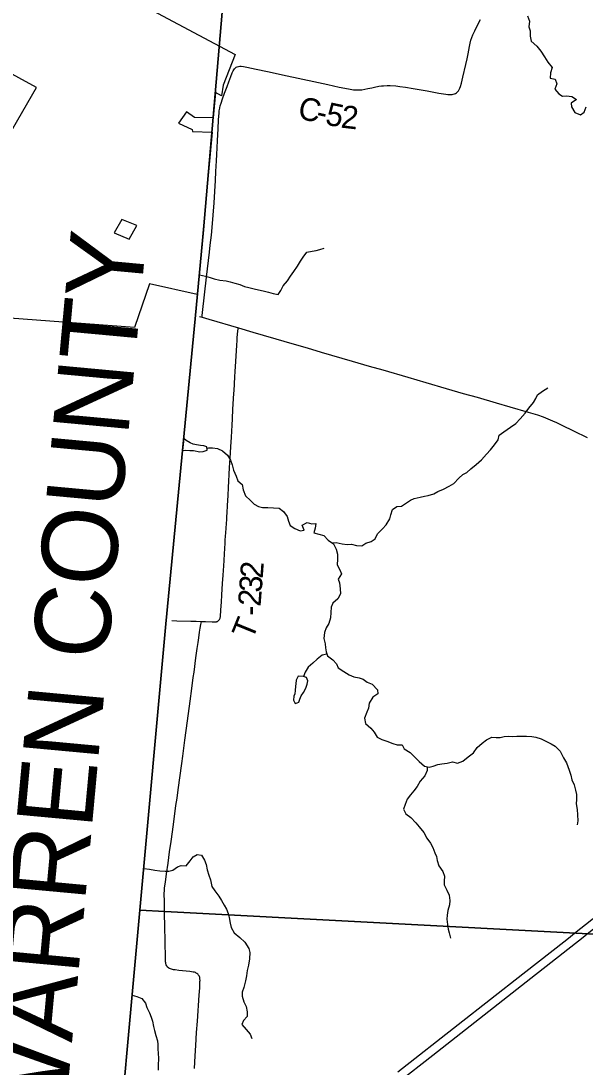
# Model space of a CAD drawing. Extents: x 1442749 to 1756758, y 235267 to 677782.
# Drawn here: x 1547500 to 1554943, y 538726 to 552520 of the extents above; entities that cross this region are included whole.
import ezdxf

# ---------------------------------------------------------------- set-up
doc = ezdxf.new("R2010")
doc.units = 0
for name, color, linetype in [('GM_X_Adjacent_County', 7, 'Continuous'), ('GM_X_Adjacent_County_Text', 7, 'Continuous'), ('GM_X_Corporation', 7, 'Continuous'), ('GM_X_County', 7, 'Continuous'), ('GM_X_County_Road', 7, 'Continuous'), ('GM_X_County_Road_Text', 7, 'Continuous'), ('GM_X_Interstate_Route', 7, 'Continuous'), ('GM_X_Minor_Lake', 7, 'Continuous'), ('GM_X_Minor_River', 7, 'Continuous'), ('GM_X_State_Route', 7, 'Continuous'), ('GM_X_Township', 7, 'Continuous'), ('GM_X_Township_Road', 7, 'Continuous'), ('GM_X_Township_Road_Text', 7, 'Continuous')]:
    doc.layers.add(name, color=color, linetype=linetype)

msp = doc.modelspace()

# ---------------------------------------------------------------- linework, layer by layer
at = {"layer": 'GM_X_Adjacent_County'}
msp.add_lwpolyline([(1551044, 562988), (1549909, 549765), (1549797, 548590), (1549411, 544570), (1549068, 540794), (1548703, 536779), (1548609, 535719), (1548059, 529500), (1548052, 529426), (1547777, 526306), (1547463, 522758), (1547324, 521188), (1546926, 516687), (1546686, 513989), (1546298, 509606), (1545822, 504298), (1545798, 504044), (1545353, 499331)], dxfattribs=at)
at = {"layer": 'GM_X_Corporation'}
for points in [[(1548824, 552881), (1550326, 552078), (1550169, 551671), (1550148, 551531), (1550065, 551575), (1550037, 551241), (1549790, 551245), (1549683, 551323), (1549577, 551172), (1549761, 551087), (1549763, 551063), (1550021, 551055), (1549823, 548911), (1549194, 549054), (1548997, 548479), (1546410, 548672)], [(1547391, 551101), (1547704, 551643), (1546537, 552279)]]:
    msp.add_lwpolyline(points, dxfattribs=at)
msp.add_lwpolyline([(1548732, 549726), (1548928, 549643), (1549031, 549821), (1548833, 549901)], close=True, dxfattribs=at)
at = {"layer": 'GM_X_County'}
msp.add_lwpolyline([(1545353, 499331), (1545798, 504044), (1545822, 504298), (1546298, 509606), (1546686, 513989), (1546926, 516687), (1547324, 521188), (1547463, 522758), (1547777, 526306), (1548052, 529426), (1548059, 529500), (1548609, 535719), (1548703, 536779), (1549068, 540794), (1549411, 544570), (1549797, 548590), (1549909, 549765), (1551044, 562988)], dxfattribs=at)
at = {"layer": 'GM_X_County_Road'}
msp.add_lwpolyline([(1549889, 548612), (1549891, 548636), (1549896, 548677), (1549950, 549139), (1549988, 549471), (1549998, 549562), (1550014, 549696), (1550023, 549794), (1550037, 549957), (1550048, 550120), (1550059, 550271), (1550067, 550415), (1550073, 550536), (1550078, 550677), (1550083, 550759), (1550089, 550847), (1550095, 550945), (1550102, 551096), (1550107, 551217), (1550114, 551306), (1550117, 551335), (1550123, 551368), (1550124, 551374), (1550129, 551399), (1550141, 551436), (1550159, 551491), (1550187, 551568), (1550221, 551657), (1550242, 551716), (1550270, 551789), (1550288, 551835), (1550299, 551860), (1550307, 551874), (1550317, 551888), (1550329, 551900), (1550341, 551908), (1550353, 551915), (1550369, 551920), (1550386, 551922), (1550407, 551922), (1550436, 551919), (1550482, 551911), (1550604, 551885), (1550755, 551853), (1551011, 551797), (1551364, 551722), (1551547, 551680), (1551700, 551647), (1551774, 551632), (1551842, 551619), (1551887, 551612), (1551926, 551610), (1551961, 551610), (1551997, 551613), (1552036, 551618), (1552077, 551627), (1552128, 551639), (1552166, 551648), (1552221, 551658), (1552257, 551663), (1552283, 551665), (1552333, 551667), (1552372, 551666), (1552445, 551662), (1552500, 551655), (1552575, 551645), (1552675, 551628), (1552859, 551596), (1553014, 551569), (1553075, 551558), (1553104, 551554), (1553130, 551551), (1553140, 551550), (1553162, 551549), (1553188, 551550), (1553204, 551552), (1553218, 551557), (1553232, 551564), (1553245, 551573), (1553260, 551586), (1553272, 551600), (1553283, 551616), (1553291, 551633), (1553299, 551654), (1553312, 551701), (1553330, 551778), (1553370, 551943), (1553388, 552020), (1553400, 552084), (1553416, 552181), (1553425, 552226), (1553435, 552264), (1553448, 552302), (1553463, 552338), (1553487, 552389), (1553516, 552447), (1553562, 552540)], dxfattribs=at)
at = {"layer": 'GM_X_Interstate_Route'}
for points in [[(1552472, 538521), (1552934, 538884), (1553241, 539126), (1554227, 539899), (1554916, 540439), (1554992, 540498), (1555622, 540996), (1556053, 541330), (1556350, 541552), (1556686, 541792), (1557003, 542010), (1557397, 542269), (1557719, 542473), (1558089, 542698), (1558328, 542835), (1558833, 543115), (1559231, 543325), (1559521, 543470), (1560001, 543699), (1560259, 543815), (1560468, 543909), (1560773, 544039), (1561542, 544359)], [(1552473, 538663), (1553270, 539288), (1554122, 539957), (1554700, 540410), (1554825, 540509), (1555156, 540770)]]:
    msp.add_lwpolyline(points, dxfattribs=at)
at = {"layer": 'GM_X_Minor_Lake'}
msp.add_line((1549648, 547014), (1549633, 546857), dxfattribs=at)
for points in [[(1549633, 546857), (1549671, 546859), (1549727, 546854), (1549777, 546857), (1549860, 546840), (1549902, 546843), (1549957, 546860), (1549952, 546902), (1549912, 546915), (1549868, 546922), (1549816, 546931), (1549772, 546941), (1549731, 546958), (1549682, 546988), (1549648, 547014)], [(1551226, 543874), (1551158, 543878), (1551131, 543828), (1551126, 543780), (1551123, 543746), (1551116, 543692), (1551113, 543648), (1551102, 543616), (1551097, 543564), (1551120, 543520), (1551145, 543529)], [(1551145, 543529), (1551167, 543537), (1551180, 543577), (1551199, 543622), (1551227, 543666), (1551257, 543721), (1551278, 543773), (1551285, 543819), (1551266, 543863), (1551226, 543874)]]:
    msp.add_lwpolyline(points, dxfattribs=at)
at = {"layer": 'GM_X_Minor_River'}
for points in [[(1554183, 552588), (1554210, 552515), (1554200, 552443), (1554219, 552390), (1554218, 552318), (1554233, 552254), (1554305, 552188), (1554360, 552123), (1554407, 552048), (1554452, 551975), (1554510, 551906), (1554487, 551836), (1554481, 551766), (1554549, 551752), (1554570, 551688), (1554543, 551620), (1554596, 551559), (1554647, 551526), (1554697, 551531), (1554767, 551522), (1554829, 551482), (1554760, 551435), (1554763, 551385), (1554807, 551312), (1554881, 551281), (1554932, 551316), (1554955, 551387)], [(1549856, 549173), (1549934, 549154), (1549996, 549136), (1550049, 549119), (1550125, 549102), (1550209, 549092), (1550260, 549079), (1550324, 549062), (1550386, 549043), (1550449, 549017), (1550507, 549004), (1550579, 548989), (1550636, 548973), (1550696, 548962), (1550764, 548941), (1550829, 548924), (1550893, 548912), (1550928, 548966), (1550959, 549025), (1551015, 549094), (1551056, 549155), (1551099, 549217), (1551147, 549288), (1551190, 549353), (1551223, 549405), (1551273, 549470), (1551341, 549482), (1551393, 549491), (1551445, 549506), (1551500, 549523)], [(1551601, 545639), (1551660, 545642), (1551736, 545625), (1551806, 545615), (1551860, 545620), (1551929, 545603), (1551999, 545600), (1552050, 545635), (1552122, 545657), (1552173, 545690), (1552203, 545758), (1552272, 545824), (1552319, 545876), (1552365, 545953), (1552380, 546007), (1552401, 546076), (1552460, 546115), (1552522, 546120), (1552573, 546157), (1552640, 546200), (1552690, 546221), (1552767, 546241), (1552823, 546252), (1552873, 546261), (1552947, 546284), (1553002, 546313), (1553075, 546347), (1553148, 546386), (1553212, 546421), (1553278, 546492), (1553329, 546537), (1553381, 546566), (1553436, 546613), (1553505, 546671), (1553575, 546734), (1553642, 546805), (1553693, 546864), (1553749, 546931), (1553796, 546994), (1553811, 547056), (1553872, 547103), (1553958, 547163), (1554027, 547210), (1554086, 547275), (1554151, 547346), (1554201, 547413), (1554262, 547488), (1554291, 547539), (1554316, 547591), (1554381, 547636), (1554450, 547680)], [(1549953, 546887), (1549975, 546889), (1550027, 546892), (1550095, 546883), (1550161, 546852), (1550227, 546792), (1550266, 546727), (1550285, 546665), (1550305, 546594), (1550340, 546518), (1550363, 546457), (1550418, 546406), (1550430, 546338), (1550463, 546259), (1550527, 546195), (1550578, 546150), (1550632, 546115), (1550685, 546102), (1550759, 546103), (1550833, 546101), (1550907, 546094), (1550962, 546049), (1551011, 545986), (1551030, 545925), (1551053, 545865), (1551114, 545829), (1551185, 545798), (1551237, 545803), (1551211, 545871), (1551275, 545908), (1551339, 545889), (1551389, 545892), (1551382, 545832), (1551365, 545770), (1551432, 545753), (1551498, 545736), (1551555, 545672), (1551624, 545623), (1551660, 545554), (1551677, 545488), (1551678, 545422), (1551674, 545348), (1551709, 545281), (1551728, 545230), (1551686, 545161), (1551701, 545111), (1551710, 545032), (1551714, 544964), (1551679, 544899), (1551616, 544842), (1551591, 544788), (1551589, 544720), (1551586, 544650), (1551560, 544575), (1551525, 544519), (1551504, 544456), (1551494, 544376), (1551513, 544307), (1551520, 544253), (1551526, 544201), (1551543, 544150), (1551614, 544097), (1551661, 544044), (1551686, 543989), (1551761, 543940), (1551830, 543896), (1551892, 543871), (1551961, 543856), (1552015, 543841), (1552066, 543799), (1552134, 543774), (1552202, 543701), (1552209, 543648), (1552144, 543604), (1552095, 543526), (1552087, 543459), (1552064, 543407), (1552033, 543327), (1552045, 543257), (1552114, 543196), (1552159, 543141), (1552201, 543074), (1552263, 543046), (1552326, 543023), (1552408, 542990), (1552462, 542976), (1552531, 542973), (1552556, 542920), (1552633, 542875), (1552696, 542812), (1552753, 542754), (1552822, 542693), (1552887, 542678), (1552938, 542693), (1553002, 542717), (1553054, 542724), (1553125, 542735)], [(1551537, 544171), (1551474, 544158), (1551407, 544105), (1551353, 544050), (1551290, 543997), (1551251, 543932), (1551226, 543874)], [(1553125, 542735), (1553193, 542750), (1553259, 542734), (1553331, 542759), (1553402, 542816), (1553471, 542868), (1553519, 542939), (1553584, 542996), (1553641, 543039), (1553712, 543076), (1553770, 543071), (1553822, 543072), (1553874, 543085), (1553934, 543090), (1553990, 543084), (1554044, 543087), (1554094, 543088), (1554170, 543091), (1554242, 543083), (1554294, 543076), (1554363, 543055), (1554494, 542986), (1554548, 542959), (1554616, 542890), (1554656, 542805), (1554699, 542736), (1554735, 542639), (1554756, 542575), (1554768, 542514), (1554797, 542448), (1554818, 542379), (1554828, 542319), (1554829, 542253), (1554826, 542195), (1554840, 542124), (1554843, 542050), (1554849, 541972), (1554838, 541920)], [(1552861, 542684), (1552861, 542634), (1552827, 542565), (1552768, 542494), (1552728, 542426), (1552685, 542367), (1552638, 542314), (1552595, 542257), (1552567, 542189), (1552548, 542125), (1552577, 542063), (1552642, 542017), (1552708, 541948), (1552753, 541893), (1552814, 541820), (1552856, 541743), (1552903, 541676), (1552936, 541621), (1552962, 541552), (1552983, 541502), (1552990, 541450), (1553013, 541377), (1553067, 541304), (1553088, 541241), (1553083, 541179), (1553084, 541127), (1553118, 541057), (1553151, 540992), (1553158, 540924), (1553152, 540866), (1553133, 540792), (1553122, 540728), (1553120, 540674), (1553129, 540604), (1553136, 540545), (1553149, 540495), (1553169, 540427)], [(1549121, 541346), (1549195, 541336), (1549267, 541321), (1549333, 541312), (1549403, 541308), (1549453, 541311), (1549503, 541320), (1549564, 541367), (1549614, 541382), (1549682, 541381), (1549732, 541446), (1549771, 541497), (1549827, 541530), (1549883, 541521), (1549922, 541452), (1549943, 541398), (1549957, 541325), (1549980, 541255), (1549999, 541194), (1550019, 541106), (1550058, 541051), (1550110, 540980), (1550145, 540923), (1550182, 540860), (1550213, 540806), (1550236, 540751), (1550248, 540697), (1550259, 540624), (1550272, 540566), (1550312, 540495), (1550387, 540436), (1550456, 540374), (1550508, 540289), (1550519, 540235), (1550517, 540151), (1550504, 540071), (1550484, 539999), (1550477, 539929), (1550461, 539863), (1550440, 539775), (1550420, 539714), (1550417, 539662), (1550440, 539585), (1550470, 539526), (1550485, 539454), (1550486, 539394), (1550437, 539339), (1550414, 539287), (1550472, 539220), (1550523, 539161), (1550548, 539104)], [(1548969, 539674), (1549031, 539657), (1549096, 539628), (1549145, 539567), (1549160, 539512), (1549194, 539440), (1549217, 539385), (1549236, 539333), (1549247, 539262), (1549262, 539206), (1549280, 539141), (1549301, 539073), (1549308, 539023), (1549305, 538961), (1549310, 538908), (1549314, 538840), (1549312, 538752), (1549309, 538686)]]:
    msp.add_lwpolyline(points, dxfattribs=at)
at = {"layer": 'GM_X_State_Route'}
msp.add_lwpolyline([(1549856, 548621), (1549889, 548612), (1549980, 548585), (1550370, 548472), (1550560, 548417), (1550695, 548377), (1550865, 548326), (1551075, 548265), (1551274, 548207), (1551460, 548152), (1551870, 548034), (1552093, 547969), (1552276, 547917), (1552604, 547822), (1552840, 547751), (1553111, 547674), (1553334, 547609), (1553517, 547557), (1553769, 547483), (1553948, 547431), (1554192, 547362), (1554314, 547326), (1554389, 547299), (1554450, 547275), (1554514, 547248), (1554565, 547225), (1554638, 547190), (1554792, 547116), (1554972, 547029)], dxfattribs=at)
at = {"layer": 'GM_X_Township'}
for points in [[(1574568, 539459), (1566007, 539894), (1561724, 540199), (1558042, 540322), (1554906, 540487), (1549399, 540777), (1549068, 540794), (1549411, 544570), (1549797, 548590), (1549909, 549765), (1551044, 562988), (1551312, 565815), (1551567, 568507), (1552180, 574981), (1554999, 574736), (1559309, 574361), (1567480, 573618), (1572928, 573040)], [(1570074, 513944), (1565959, 517426), (1564776, 518401), (1563405, 519560), (1563130, 519793), (1562277, 520514), (1559821, 521555), (1557365, 522585), (1554150, 523932), (1552094, 524698), (1549956, 525494), (1547777, 526306), (1548052, 529426), (1548059, 529500), (1548609, 535719), (1548703, 536779), (1549068, 540794), (1549399, 540777), (1554906, 540487), (1558042, 540322), (1561724, 540199), (1566007, 539894), (1574568, 539459)]]:
    msp.add_lwpolyline(points, dxfattribs=at)
at = {"layer": 'GM_X_Township_Road'}
for points in [[(1549881, 544602), (1549933, 544600), (1550025, 544596), (1550049, 544595), (1550067, 544595), (1550074, 544596), (1550080, 544597), (1550086, 544599), (1550091, 544601), (1550096, 544603), (1550104, 544609), (1550112, 544617), (1550118, 544626), (1550123, 544635), (1550127, 544644), (1550129, 544653), (1550131, 544663), (1550132, 544674), (1550134, 544695), (1550136, 544724), (1550138, 544755), (1550144, 544854), (1550151, 544951), (1550161, 545101), (1550169, 545211), (1550177, 545334), (1550182, 545404), (1550187, 545495), (1550194, 545634), (1550196, 545678), (1550199, 545721), (1550203, 545776), (1550207, 545827), (1550212, 545896), (1550216, 545942), (1550218, 545987), (1550221, 546035), (1550226, 546129), (1550233, 546261), (1550238, 546367), (1550242, 546451), (1550247, 546538), (1550252, 546633), (1550259, 546755), (1550269, 546903), (1550277, 547032), (1550285, 547190), (1550289, 547273), (1550296, 547401), (1550300, 547466), (1550309, 547612), (1550311, 547644), (1550321, 547828), (1550325, 547896), (1550333, 548029), (1550347, 548243), (1550351, 548306), (1550354, 548340), (1550358, 548391), (1550363, 548427), (1550368, 548458), (1550370, 548472)], [(1549396, 540741), (1549394, 540838), (1549392, 540940), (1549390, 540980), (1549390, 541015), (1549393, 541053), (1549396, 541089), (1549406, 541162), (1549421, 541275), (1549441, 541413), (1549462, 541564), (1549480, 541702), (1549511, 541925), (1549545, 542173), (1549559, 542272), (1549574, 542382), (1549621, 542729), (1549634, 542825), (1549663, 543038), (1549699, 543290), (1549732, 543552), (1549755, 543718), (1549774, 543862), (1549784, 543934), (1549809, 544122), (1549826, 544246), (1549837, 544323), (1549846, 544387), (1549856, 544461), (1549864, 544514), (1549873, 544563), (1549880, 544598), (1549881, 544602)], [(1549490, 544612), (1549555, 544610), (1549740, 544606), (1549810, 544604), (1549871, 544602), (1549881, 544602)], [(1549791, 538706), (1549800, 538872), (1549807, 539009), (1549818, 539181), (1549828, 539329), (1549850, 539675), (1549858, 539771), (1549860, 539802), (1549862, 539852), (1549863, 539869), (1549862, 539891), (1549859, 539905), (1549855, 539918), (1549851, 539929), (1549839, 539944), (1549832, 539952), (1549822, 539960), (1549813, 539965), (1549801, 539971), (1549789, 539975), (1549772, 539979), (1549751, 539982), (1549729, 539985), (1549581, 540001), (1549536, 540006), (1549512, 540010), (1549498, 540012), (1549485, 540015), (1549471, 540020), (1549460, 540025), (1549450, 540032), (1549435, 540045), (1549425, 540059), (1549417, 540074), (1549412, 540090), (1549411, 540098), (1549409, 540112), (1549408, 540130), (1549409, 540166), (1549399, 540589), (1549396, 540741)]]:
    msp.add_lwpolyline(points, dxfattribs=at)

# ---------------------------------------------------------------- texts
at = {"layer": 'GM_X_Adjacent_County_Text'}
msp.add_text('WARREN COUNTY', height=1000, rotation=84.716, dxfattribs=at).set_placement((1548057, 537785))
at = {"layer": 'GM_X_County_Road_Text'}
for s, rotation, p in [('C', 347.6892, (1551139, 551236)), ('5', 348.1216, (1551503, 551157)), ('2', 353.2548, (1551712, 551114)), ('-', 347.765, (1551380, 551184))]:
    msp.add_text(s, height=300, rotation=rotation, dxfattribs=at).set_placement(p)
at = {"layer": 'GM_X_Township_Road_Text'}
for s, rotation, p in [('2', 85.7428, (1550689, 545161)), ('3', 85.7152, (1550675, 544977)), ('2', 85.6141, (1550661, 544792)), ('-', 89.8532, (1550660, 544675)), ('T', 67.8727, (1550552, 544345))]:
    msp.add_text(s, height=300, rotation=rotation, dxfattribs=at).set_placement(p)

doc.saveas('drawing.dxf')
